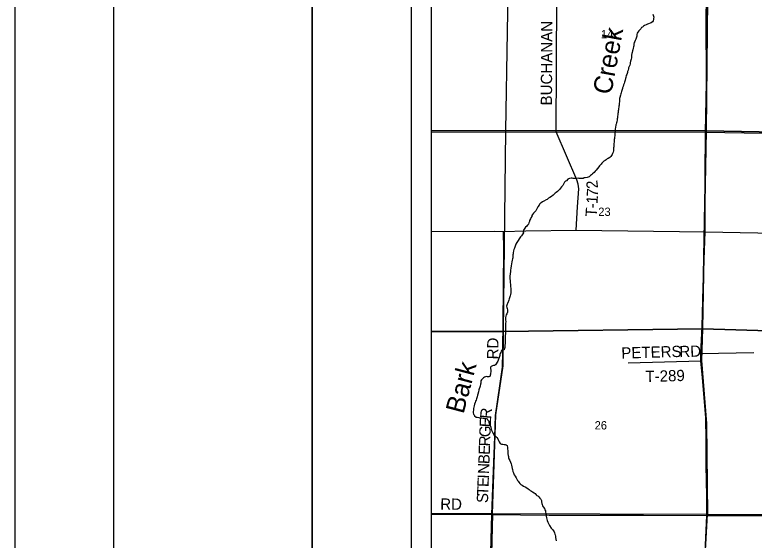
# Model space of a CAD drawing. Extents: x 36.7 to 70.7, y 0 to 22.
# Drawn here: x 36.693 to 40.424, y 14.842 to 17.492 of the extents above; entities that cross this region are included whole.
import ezdxf

# ---------------------------------------------------------------- set-up
doc = ezdxf.new("R2010")
doc.units = 0
for name, color, linetype in [('Default', 7, 'Continuous'), ('GM_X_County_Road', 7, 'Continuous'), ('GM_X_County_Road_Text', 7, 'Continuous'), ('GM_X_Minor_River', 7, 'Continuous'), ('GM_X_Minor_River_Text', 7, 'Continuous'), ('GM_X_Section', 7, 'Continuous'), ('GM_X_Section_Text', 7, 'Continuous'), ('GM_X_Township_Road', 7, 'Continuous'), ('GM_X_Township_Road_Text', 7, 'Continuous'), ('SH_Border', 7, 'Continuous'), ('SH_Cut_Line', 7, 'Continuous'), ('SH_Data', 7, 'Continuous')]:
    doc.layers.add(name, color=color, linetype=linetype)

msp = doc.modelspace()

# ---------------------------------------------------------------- linework, layer by layer
at = {"layer": 'Default'}
for points in [[(38.7934, 17.9022), (38.7934, 16.9058), (39.1708, 16.9074), (39.1871, 17.9045)], [(38.7934, 16.9058), (38.7934, 15.8936), (39.1592, 15.8941), (39.1708, 16.9074)], [(38.7934, 15.8936), (38.7934, 14.9765), (39.1038, 14.9743), (39.121, 15.4744), (39.1577, 15.7205), (39.1592, 15.8941)], [(38.7934, 14.9765), (38.7934, 14.0969), (39.082, 14.0969), (39.1038, 14.9743)], [(39.082, 14.0969), (40.1392, 14.0969), (40.1892, 14.9717), (39.1038, 14.9743)]]:
    msp.add_lwpolyline(points, close=True, dxfattribs=at)
at = {"layer": 'GM_X_County_Road'}
msp.add_line((38.7934, 14.9734), (39.1004, 14.9709), dxfattribs=at)
for points in [[(40.1787, 16.9), (40.1827, 17.1484), (40.1815, 17.4785), (40.1885, 17.8171), (40.2033, 18.191), (40.2175, 18.4104)], [(40.1763, 16.3968), (40.1771, 16.6813), (40.1787, 16.9)], [(38.7934, 16.3995), (39.1122, 16.3998), (39.1597, 16.3994), (39.2718, 16.4014)], [(39.2718, 16.4014), (39.5265, 16.4061), (40.1763, 16.3968), (41.2394, 16.377)], [(40.1853, 14.9672), (40.1846, 15.0633), (40.1825, 15.221), (40.1819, 15.346), (40.1799, 15.4588), (40.163, 15.6608), (40.1541, 15.746), (40.1556, 15.7828), (40.1611, 15.9192), (40.1658, 16.1181), (40.1763, 16.3968)], [(39.1004, 14.9709), (39.3903, 14.9674), (39.7009, 14.9673), (39.866, 14.9673), (40.1853, 14.9672), (40.6951, 14.9659), (41.0895, 14.9744), (41.1597, 14.9749), (41.1747, 14.9764), (41.1765, 14.9766), (41.1844, 14.9819)], [(40.1402, 14.0969), (40.1568, 14.4677), (40.1766, 14.7804), (40.1853, 14.9672)]]:
    msp.add_lwpolyline(points, dxfattribs=at)
at = {"layer": 'GM_X_Minor_River'}
for points in [[(39.9121, 17.4949), (39.9143, 17.4895), (39.9154, 17.4842), (39.9172, 17.4789), (39.9168, 17.4721), (39.916, 17.4671), (39.9148, 17.4614), (39.9109, 17.4566), (39.904, 17.4506), (39.8987, 17.4491), (39.8911, 17.4454), (39.885, 17.4435), (39.8793, 17.4417), (39.8701, 17.4373), (39.8648, 17.4339), (39.8605, 17.4294)], [(39.8605, 17.4294), (39.856, 17.4272), (39.8513, 17.4204), (39.8479, 17.4155), (39.8421, 17.4102), (39.8371, 17.4034), (39.8344, 17.3982), (39.8324, 17.3925), (39.8312, 17.3842), (39.83, 17.3792), (39.8261, 17.3679), (39.8241, 17.3626), (39.821, 17.3569), (39.8191, 17.3513), (39.8175, 17.3433), (39.8162, 17.3357), (39.8143, 17.3293), (39.8131, 17.3236), (39.8111, 17.3153), (39.8095, 17.3092), (39.8079, 17.3009), (39.8071, 17.2964), (39.8058, 17.2873), (39.8054, 17.2808), (39.8042, 17.2748), (39.8029, 17.2683), (39.8014, 17.2626), (39.8006, 17.2581), (39.7989, 17.2501), (39.7977, 17.2448), (39.7958, 17.2373), (39.7926, 17.2301), (39.7907, 17.2248), (39.7895, 17.2191), (39.7879, 17.2119), (39.7855, 17.2055), (39.7843, 17.2006), (39.7808, 17.1904), (39.7785, 17.1855), (39.7761, 17.1756), (39.7741, 17.1699), (39.7729, 17.1616), (39.7709, 17.1567), (39.7701, 17.1521), (39.7678, 17.1457), (39.7643, 17.1378), (39.7627, 17.1302), (39.7599, 17.1238), (39.7591, 17.1192), (39.756, 17.1094), (39.754, 17.1041), (39.7521, 17.0973), (39.7509, 17.0924), (39.7489, 17.0856), (39.7465, 17.0753), (39.7453, 17.0697), (39.7445, 17.0617), (39.7444, 17.0564), (39.744, 17.0518), (39.7435, 17.0462), (39.7435, 17.0408), (39.7423, 17.0355), (39.7418, 17.031), (39.741, 17.0249), (39.7398, 17.0192), (39.739, 17.0128), (39.7381, 17.0071), (39.7373, 16.9984), (39.7368, 16.9931), (39.7356, 16.9866), (39.7348, 16.981), (39.7339, 16.9722), (39.7324, 16.9669), (39.7319, 16.9616), (39.7307, 16.9518), (39.7291, 16.9469), (39.7279, 16.9408), (39.7267, 16.9359), (39.725, 16.923), (39.7234, 16.9158), (39.7226, 16.9105), (39.7222, 16.9029), (39.7217, 16.898), (39.7217, 16.8934), (39.7212, 16.8885), (39.7204, 16.8813), (39.7196, 16.8748), (39.7187, 16.868), (39.7179, 16.862), (39.7171, 16.857), (39.717, 16.8487), (39.7162, 16.8419), (39.7157, 16.8365), (39.7152, 16.8259), (39.7144, 16.8202), (39.7139, 16.8111), (39.7135, 16.8058), (39.7122, 16.7982), (39.7099, 16.7918), (39.7076, 16.7869), (39.7045, 16.7812)], [(39.7045, 16.7812), (39.7014, 16.7763), (39.696, 16.7718), (39.6872, 16.767), (39.6819, 16.7644), (39.6765, 16.7603), (39.6716, 16.7565), (39.6658, 16.7528), (39.6605, 16.7479), (39.6555, 16.7431), (39.6516, 16.7385), (39.6439, 16.7299), (39.6409, 16.725), (39.6332, 16.7167), (39.6262, 16.7077), (39.622, 16.7028), (39.6163, 16.6968), (39.609, 16.69), (39.6028, 16.684), (39.5983, 16.681), (39.5914, 16.675), (39.586, 16.6724), (39.5807, 16.6706), (39.5719, 16.6695), (39.5655, 16.6689), (39.5605, 16.6666), (39.5548, 16.6663), (39.5465, 16.666), (39.5404, 16.6661), (39.5355, 16.6669), (39.523, 16.6667), (39.5158, 16.6664), (39.5108, 16.6664), (39.5055, 16.6672), (39.4998, 16.6669), (39.4926, 16.6662), (39.4877, 16.6651), (39.4831, 16.6618), (39.4773, 16.6546), (39.4727, 16.6524), (39.4678, 16.6471), (39.4639, 16.6415), (39.4585, 16.6313), (39.4519, 16.6234), (39.4466, 16.6174), (39.4427, 16.6125), (39.4369, 16.6061), (39.4312, 16.6012), (39.4247, 16.596), (39.4201, 16.5918), (39.4147, 16.5873), (39.409, 16.5821), (39.4013, 16.5753), (39.3933, 16.5705), (39.3868, 16.5664), (39.3788, 16.5604), (39.3738, 16.5582), (39.3624, 16.5515), (39.3562, 16.5477), (39.3497, 16.5436), (39.3452, 16.5414), (39.3413, 16.5357), (39.3386, 16.5312), (39.3332, 16.5225), (39.3293, 16.5161), (39.3262, 16.5097), (39.3224, 16.5033), (39.3151, 16.4965), (39.3108, 16.4913), (39.3047, 16.4849), (39.3024, 16.4796), (39.3015, 16.4747), (39.2969, 16.4679), (39.295, 16.463), (39.2911, 16.4547), (39.2899, 16.4497), (39.2871, 16.4422), (39.2848, 16.4361), (39.2809, 16.4301), (39.2763, 16.4264), (39.271, 16.4203), (39.2664, 16.4158), (39.2636, 16.4102), (39.2594, 16.4053), (39.2586, 16.3973), (39.2604, 16.392), (39.2562, 16.3863), (39.2531, 16.3818), (39.2492, 16.3773), (39.2454, 16.3713), (39.2381, 16.3618), (39.2338, 16.3539), (39.2292, 16.3479), (39.2261, 16.343), (39.2222, 16.3347), (39.2171, 16.3199), (39.2144, 16.3143), (39.212, 16.3075), (39.2104, 16.3018), (39.208, 16.2904), (39.208, 16.2859)], [(39.208, 16.2859), (39.2068, 16.2813), (39.2055, 16.2665), (39.2043, 16.2616), (39.2027, 16.254), (39.2011, 16.2461), (39.1991, 16.2355), (39.1971, 16.2253), (39.1954, 16.2135), (39.1942, 16.2036), (39.1937, 16.1987), (39.1932, 16.1843), (39.1919, 16.1756), (39.1914, 16.1653), (39.1914, 16.1608), (39.1921, 16.1524), (39.1924, 16.1479), (39.1927, 16.1395), (39.1937, 16.1327), (39.1944, 16.1273), (39.1951, 16.1209), (39.1958, 16.1114), (39.1961, 16.1049), (39.1959, 16.0939), (39.1955, 16.0886), (39.1947, 16.0806), (39.1935, 16.0746), (39.1915, 16.0689), (39.1903, 16.0644), (39.1883, 16.0583), (39.1864, 16.053), (39.1848, 16.0477), (39.1821, 16.0432), (39.1801, 16.0364), (39.177, 16.0315), (39.1755, 16.0269), (39.1747, 16.0224), (39.1757, 16.0148), (39.1779, 16.0098), (39.1794, 16.0034), (39.1801, 15.9973), (39.1796, 15.9916), (39.1761, 15.984), (39.1734, 15.9791), (39.1718, 15.9719), (39.1695, 15.9655), (39.1686, 15.9564), (39.1693, 15.9507), (39.1704, 15.9442), (39.1699, 15.9348), (39.1698, 15.9298), (39.1701, 15.9249), (39.1693, 15.9169), (39.1692, 15.9101), (39.1688, 15.9048), (39.1691, 15.8968), (39.1689, 15.8831), (39.1684, 15.874), (39.1679, 15.8646), (39.1678, 15.8539), (39.1673, 15.8452), (39.1673, 15.8406), (39.1668, 15.8338), (39.166, 15.8262), (39.1655, 15.819), (39.1651, 15.8133), (39.1646, 15.8088), (39.1623, 15.802), (39.1562, 15.7998), (39.1516, 15.7998), (39.1474, 15.7949), (39.1462, 15.7892), (39.1431, 15.784), (39.1415, 15.7787), (39.1403, 15.7726), (39.1384, 15.7677), (39.1352, 15.7586), (39.1341, 15.7541), (39.1302, 15.7454), (39.1278, 15.7405), (39.1224, 15.7318), (39.1182, 15.7269), (39.1136, 15.7235), (39.1083, 15.7228), (39.1037, 15.7217), (39.0972, 15.7184), (39.0934, 15.7139), (39.0933, 15.7074), (39.0947, 15.6998), (39.0947, 15.6953), (39.093, 15.6793), (39.0926, 15.6744), (39.0914, 15.6687), (39.086, 15.6665), (39.0788, 15.6662), (39.0739, 15.6666), (39.0689, 15.6659), (39.0632, 15.6637), (39.0583, 15.6611), (39.054, 15.6558), (39.0479, 15.6506)], [(39.0479, 15.6506), (39.0456, 15.6461), (39.0455, 15.6392), (39.0447, 15.6335), (39.0439, 15.6286), (39.0411, 15.6188), (39.0403, 15.6135), (39.0372, 15.6055), (39.0352, 15.6002), (39.0336, 15.59), (39.0304, 15.5779), (39.0288, 15.5734), (39.0265, 15.5654), (39.0233, 15.5556), (39.021, 15.5488), (39.0186, 15.5423), (39.0167, 15.5367), (39.0135, 15.528), (39.0108, 15.5193), (39.0092, 15.5124), (39.008, 15.5052), (39.0071, 15.4973), (39.0063, 15.4901), (39.0066, 15.4836), (39.0084, 15.4779), (39.0106, 15.4733), (39.0132, 15.4687), (39.0207, 15.463), (39.0264, 15.4618), (39.034, 15.4613), (39.0385, 15.4597), (39.0442, 15.4593), (39.0495, 15.4589), (39.0567, 15.4573), (39.0651, 15.4564), (39.0715, 15.4556), (39.0768, 15.4544), (39.0809, 15.4479), (39.0846, 15.4429), (39.0857, 15.4368), (39.0872, 15.4315), (39.0912, 15.4205), (39.0949, 15.4113), (39.0971, 15.4026), (39.0985, 15.3972), (39.1015, 15.3892), (39.1059, 15.3827), (39.1126, 15.372), (39.119, 15.3666), (39.1262, 15.3605), (39.1306, 15.3525), (39.1343, 15.3445), (39.1377, 15.3372), (39.1421, 15.3299), (39.1489, 15.3257), (39.1557, 15.3256), (39.1622, 15.3252), (39.1675, 15.324), (39.172, 15.3232), (39.1773, 15.3201), (39.1798, 15.3087), (39.1801, 15.3003), (39.1819, 15.2946), (39.1818, 15.2779), (39.1832, 15.2684), (39.1846, 15.2638), (39.1849, 15.2566), (39.1864, 15.2517), (39.1905, 15.2444), (39.1942, 15.2356), (39.1986, 15.2265), (39.1997, 15.2204), (39.2011, 15.2113), (39.2033, 15.204), (39.2051, 15.1987), (39.2069, 15.188), (39.2095, 15.1823), (39.2132, 15.172), (39.218, 15.1651), (39.2229, 15.1556), (39.2258, 15.1495), (39.2295, 15.1426), (39.234, 15.1388), (39.2374, 15.1338), (39.2415, 15.1285), (39.2471, 15.1235), (39.2532, 15.1188), (39.2607, 15.115), (39.2679, 15.1103), (39.2777, 15.1057), (39.2844, 15.1014), (39.2893, 15.0972), (39.2942, 15.0926), (39.2999, 15.0887), (39.3063, 15.0852), (39.3142, 15.0806), (39.3187, 15.0771), (39.3232, 15.0714), (39.3281, 15.0679), (39.3326, 15.0656), (39.3382, 15.0602)], [(39.3382, 15.0602), (39.342, 15.0545), (39.3468, 15.0491), (39.3502, 15.0423), (39.3512, 15.035), (39.3534, 15.027), (39.3545, 15.0213), (39.3567, 15.0152), (39.3596, 15.0095), (39.3656, 15.0011), (39.3682, 14.9946), (39.3704, 14.9893), (39.3719, 14.9843), (39.3733, 14.9748), (39.374, 14.9691), (39.3743, 14.9638), (39.3761, 14.9554), (39.3779, 14.9474), (39.3797, 14.9406), (39.3823, 14.933), (39.3856, 14.9261), (39.392, 14.9154), (39.4005, 14.9032), (39.4088, 14.894), (39.4118, 14.8886), (39.414, 14.8833), (39.4158, 14.8787), (39.4176, 14.873), (39.4199, 14.8684), (39.4217, 14.8623), (39.4224, 14.8559), (39.4238, 14.8475), (39.4248, 14.8384)]]:
    msp.add_lwpolyline(points, dxfattribs=at)
at = {"layer": 'GM_X_Section'}
for points in [[(40.1915, 17.9066), (40.1819, 16.9057), (39.1708, 16.9074), (39.1871, 17.9045)], [(41.2806, 17.8858), (41.2523, 16.9188), (41.2509, 16.8855), (40.1819, 16.9057), (40.1915, 17.9066)], [(40.1819, 16.9057), (40.1632, 15.9076), (39.1592, 15.8941), (39.1708, 16.9074)], [(41.2509, 16.8855), (41.2283, 15.9252), (41.2265, 15.8756), (40.1632, 15.9076), (40.1819, 16.9057)], [(40.1632, 15.9076), (40.1588, 15.7484), (40.1834, 15.4299), (40.1892, 14.9717), (39.1038, 14.9743), (39.121, 15.4744), (39.1577, 15.7205), (39.1592, 15.8941)], [(41.2265, 15.8756), (41.1785, 14.9796), (41.1776, 14.9705), (40.1892, 14.9717), (40.1834, 15.4299), (40.1588, 15.7484), (40.1632, 15.9076)]]:
    msp.add_lwpolyline(points, close=True, dxfattribs=at)
at = {"layer": 'GM_X_Township_Road'}
for p, q in [((39.4251, 16.9015), (39.4287, 17.9045)), ((38.7934, 16.8991), (39.4251, 16.9015)), ((39.1553, 15.7912), (39.1556, 15.8108)), ((40.1556, 15.7828), (40.4222, 15.7877)), ((39.7887, 15.7356), (40.1541, 15.746))]:
    msp.add_line(p, q, dxfattribs=at)
for points in [[(40.7272, 19.8287), (40.1721, 19.8397), (40.1059, 19.841), (40.026, 19.8426), (39.8966, 19.8451), (39.8755, 19.8455), (39.8261, 19.8465), (39.7798, 19.8474), (39.6885, 19.8492), (39.6095, 19.8508), (39.5528, 19.8519), (39.4534, 19.8539), (39.1666, 19.8625), (39.1212, 19.8604), (39.0949, 19.8611), (39.0385, 19.8625), (38.9743, 19.8619), (38.9071, 19.8613), (38.8465, 19.8607), (38.7934, 19.8608), (38.7934, 14.0969)], [(39.5265, 16.4061), (39.533, 16.5233), (39.5393, 16.6132), (39.5352, 16.6369), (39.5298, 16.6594), (39.4251, 16.9015)], [(39.4251, 16.9015), (40.1787, 16.9), (41.2501, 16.8809)], [(39.1556, 15.8108), (39.1575, 15.9333), (39.1605, 16.3074), (39.1597, 16.3994)], [(39.1004, 14.9709), (39.1052, 15.1053), (39.115, 15.3634), (39.1194, 15.4712), (39.1404, 15.621), (39.154, 15.7138), (39.1553, 15.7912)], [(39.083, 14.0969), (39.0873, 14.4651), (39.1004, 14.9709)]]:
    msp.add_lwpolyline(points, dxfattribs=at)
at = {"layer": 'SH_Border'}
for points in [[(37.1934, 21.4969), (38.1934, 21.4969), (38.1934, 0.4969), (37.1934, 0.4969)], [(38.1934, 21.4969), (70.1934, 21.4969), (70.1934, 0.4969), (38.1934, 0.4969)]]:
    msp.add_lwpolyline(points, close=True, dxfattribs=at)
at = {"layer": 'SH_Cut_Line'}
msp.add_lwpolyline([(36.6934, -0.0031), (70.6934, -0.0031), (70.6934, 21.9969), (36.6934, 21.9969)], close=True, dxfattribs=at)
at = {"layer": 'SH_Data'}
for p, q in [((38.6934, 20.9969), (38.6934, 13.9969)), ((38.7934, 20.8969), (38.7934, 14.0969))]:
    msp.add_line(p, q, dxfattribs=at)

# ---------------------------------------------------------------- texts
at = {"layer": 'GM_X_County_Road_Text'}
msp.add_text('RD', height=0.05682, rotation=359.5063, dxfattribs=at).set_placement((38.8398, 14.9959))
at = {"layer": 'GM_X_Minor_River_Text'}
for s, height, rotation, p in [('Creek', 0.09474, 79.537, (39.7025, 17.0852)), ('Bark', 0.09475, 75.2004, (38.9572, 15.4752))]:
    msp.add_text(s, height=height, rotation=rotation, dxfattribs=at).set_placement(p)
at = {"layer": 'GM_X_Section_Text'}
for s, p in [('14', (39.6509, 17.373)), ('23', (39.6376, 16.4773)), ('26', (39.6192, 15.4002))]:
    msp.add_text(s, height=0.04186, rotation=0, dxfattribs=at).set_placement(p)
at = {"layer": 'GM_X_Township_Road_Text'}
for s, height, rotation, p in [('BUCHANAN', 0.05682, 89.7573, (39.4039, 17.0344)), ('2', 0.0568, 96.5328, (39.6367, 16.6178)), ('7', 0.0568, 87.5149, (39.6355, 16.5731)), ('1', 0.0568, 86.4772, (39.6333, 16.5371)), ('-', 0.0568, 86.2227, (39.6317, 16.5135)), ('T', 0.0568, 86.1443, (39.6289, 16.471)), ('RD', 0.05682, 89.0303, (39.1323, 15.7532)), ('PETERS', 0.05682, 1.6433, (39.7543, 15.7574)), ('RD', 0.05682, 1.6433, (40.0472, 15.7647)), ('T-289', 0.05682, 1.6433, (39.8762, 15.6392)), ('R', 0.0568, 84.5236, (39.0968, 15.4522)), ('E', 0.0568, 87.5822, (39.095, 15.4106)), ('G', 0.0568, 87.843, (39.0931, 15.3607)), ('R', 0.0568, 87.845, (39.0914, 15.3141)), ('E', 0.0568, 87.8475, (39.0898, 15.2716)), ('B', 0.0568, 87.8411, (39.088, 15.2249)), ('N', 0.0568, 87.8466, (39.0861, 15.175)), ('E', 0.0568, 87.8446, (39.0837, 15.1092)), ('I', 0.0568, 87.8467, (39.0853, 15.1517)), ('T', 0.0568, 87.8438, (39.0821, 15.0667)), ('S', 0.0568, 87.8471, (39.0806, 15.0284))]:
    msp.add_text(s, height=height, rotation=rotation, dxfattribs=at).set_placement(p)

doc.saveas('drawing.dxf')
